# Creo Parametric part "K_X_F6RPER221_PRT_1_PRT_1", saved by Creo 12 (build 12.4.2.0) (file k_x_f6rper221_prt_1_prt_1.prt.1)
Units: Custom; MM, KILOGRAM, SECS

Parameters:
  PTC_WM_ITERATION = "0"
  PTC_WM_VERSION = "-.0"
  PTC_WM_LIFECYCLE_STATE = "In Work"
  PTC_WM_LIFECYCLE = "MO_CADDocument"
  PTC_WM_CREATED_BY = "Maximilian Roepper (Z0017RMS: MO)"
  PTC_WM_CREATED_ON = "18-Sep-26 11:36:42 AM"
  PTC_WM_MODIFIED_BY = "Maximilian Roepper (Z0017RMS: MO)"
  PTC_WM_MODIFIED_ON = "18-Sep-26 11:36:46 AM"
  PDMLINKNUMBER = "PDM000071455071"
  PTC_WM_NAME = "k_x_f6rper221_prt_1_prt_1.prt"
  PTC_WM_NUMBER = "PDM000071455071"

Other parameters: WEIGHT, WEIGHT_FACTOR, WEIGHT_ADD, _MASS_TEMP, _DIFF_TEMP, MC_ERRORS, SUPPLIER

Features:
  1. coordinate system
  2. datum plane "PRT_YZ"
  3. datum plane "PRT_XY"
  4. datum plane "PRT_XZ"
  5. coordinate system
  6. datum axis
  7. datum axis
  8. datum axis
  9. coordinate system
  10. imported feature
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
Other named items: PRT, SIEMENS_MO, DRW_VIEW_ORG, PRT_X, PRT_Y, PRT_Z, CS0, ROUGH_GROB

Layers: 00_STD_CSYS-KSYS, 01_STD_PLANES-EBENEN, 02_STD_AXES-ACHSEN, 03_STD_CSYS-KSYS, 24_IMPORT_FEAT-IMPORT_KE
